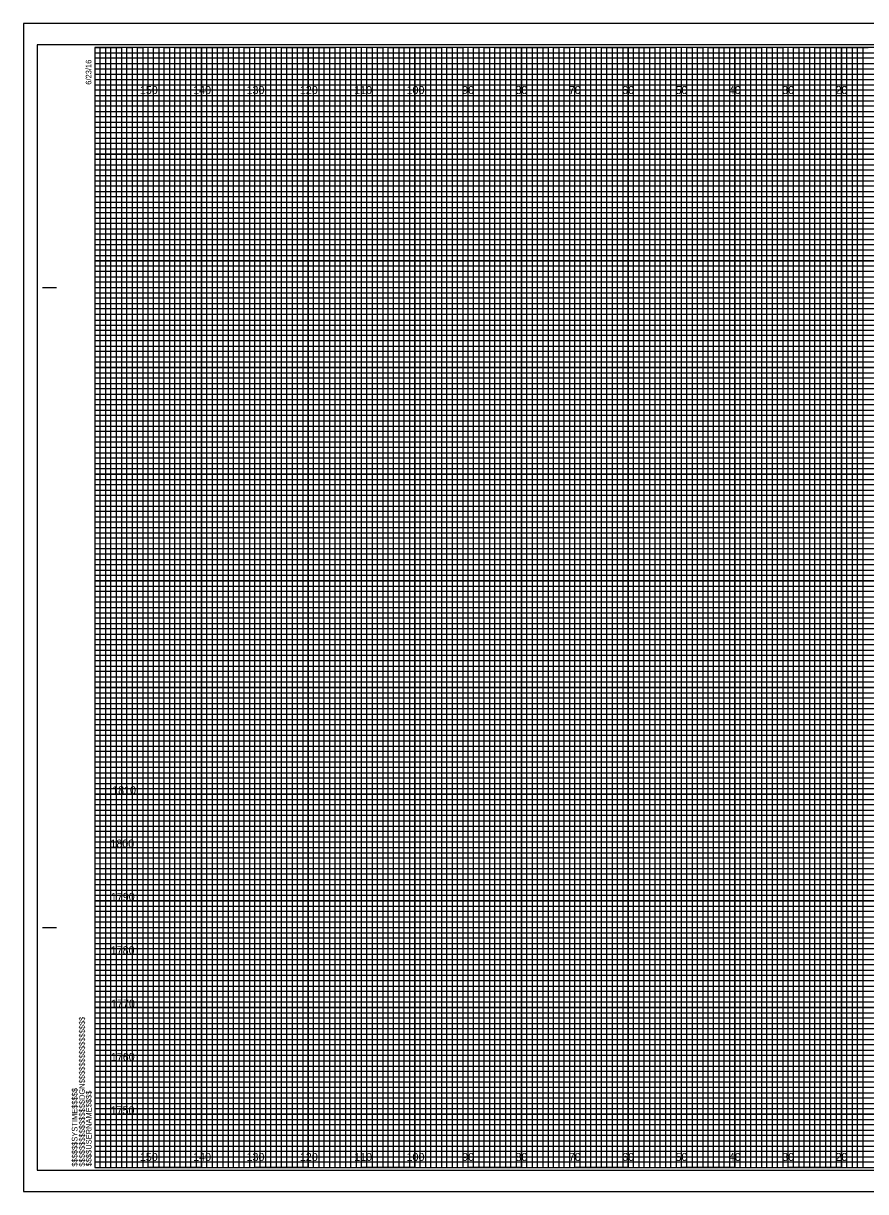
# Model space of a CAD drawing. Extents: x -13 to 323, y -5 to 874.
# Drawn here: x -13.4 to 144.5, y 655.5 to 874.5 of the extents above; entities that cross this region are included whole.
import ezdxf

# ---------------------------------------------------------------- set-up
doc = ezdxf.new("R2010")
doc.units = 0
for name, color, linetype in [('Prop XS Earthwork Shape', 7, 'Continuous'), ('Raster_Level_0', 7, 'Continuous'), ('Scratch_Level_1', 7, 'Continuous'), ('Scratch_Level_3', 7, 'Continuous'), ('Sheet Cross Section CELL', 7, 'Continuous'), ('Sheet Cross Section Grid Minor 1 CELL', 7, 'Continuous'), ('Sheet Cross Section Grid Minor 2 CELL', 7, 'Continuous'), ('Sheet Cutting Line CELL', 7, 'Continuous'), ('Sheet DOT Grid CELL', 7, 'Continuous'), ('Sheet Plot Border Inside CELL', 7, 'Continuous'), ('Sheet Plot Border Outside CELL', 7, 'Continuous')]:
    doc.layers.add(name, color=color, linetype=linetype)

msp = doc.modelspace()

# ---------------------------------------------------------------- linework, layer by layer
at = {"layer": 'Prop XS Earthwork Shape'}
for points in [[(0, 870), (5, 870), (5, 660), (15, 660), (15, 870), (25, 870), (25, 660), (35, 660), (35, 870), (45, 870), (45, 660), (55, 660), (55, 870), (65, 870), (65, 660), (75, 660), (75, 870), (85, 870), (85, 660), (95, 660), (95, 870), (105, 870), (105, 660), (115, 660), (115, 870), (125, 870), (125, 660), (135, 660), (135, 870), (145, 870)], [(0, 865), (275, 865)], [(0, 845), (320, 845), (320, 855), (0, 855)], [(0, 825), (320, 825), (320, 835), (0, 835)], [(0, 805), (320, 805), (320, 815), (0, 815)], [(0, 785), (320, 785), (320, 795), (0, 795)], [(0, 765), (320, 765), (320, 775), (0, 775)], [(0, 745), (320, 745), (320, 755), (0, 755)], [(0, 725), (320, 725), (320, 735), (0, 735)], [(0, 705), (320, 705), (320, 715), (0, 715)], [(0, 685), (320, 685), (320, 695), (0, 695)], [(0, 665), (320, 665), (320, 675), (0, 675)]]:
    msp.add_lwpolyline(points, dxfattribs=at)
at = {"layer": 'Scratch_Level_1'}
for p, q in [((10, 870), (0, 870)), ((10, 660), (10, 870)), ((30, 870), (20, 870)), ((20, 870), (20, 660)), ((30, 660), (30, 870)), ((50, 870), (40, 870)), ((40, 870), (40, 660)), ((50, 660), (50, 870)), ((70, 870), (60, 870)), ((60, 870), (60, 660)), ((70, 660), (70, 870)), ((90, 870), (80, 870)), ((80, 870), (80, 660)), ((90, 660), (90, 870)), ((110, 870), (100, 870)), ((100, 870), (100, 660)), ((110, 660), (110, 870)), ((130, 870), (120, 870)), ((120, 870), (120, 660)), ((130, 660), (130, 870)), ((150, 870), (140, 870)), ((140, 870), (140, 660)), ((20, 660), (10, 660)), ((40, 660), (30, 660)), ((60, 660), (50, 660)), ((80, 660), (70, 660)), ((100, 660), (90, 660)), ((120, 660), (110, 660)), ((140, 660), (130, 660))]:
    msp.add_line(p, q, dxfattribs=at)
for points in [[(0, 860), (320, 860), (320, 850), (0, 850)], [(0, 840), (320, 840), (320, 830), (0, 830)], [(0, 820), (320, 820), (320, 810), (0, 810)], [(0, 800), (320, 800), (320, 790), (0, 790)], [(0, 780), (320, 780), (320, 770), (0, 770)], [(0, 760), (320, 760), (320, 750), (0, 750)], [(0, 740), (320, 740), (320, 730), (0, 730)], [(0, 720), (320, 720), (320, 710), (0, 710)], [(0, 700), (320, 700), (320, 690), (0, 690)], [(0, 680), (320, 680), (320, 670), (0, 670)]]:
    msp.add_lwpolyline(points, dxfattribs=at)
at = {"layer": 'Sheet Cross Section CELL'}
for p, q in [((-9.8, 825), (-7.3, 825)), ((-9.7, 825), (-7.2, 825)), ((-9.8, 705), (-7.3, 705)), ((-9.7, 705), (-7.2, 705)), ((0, 660), (0, 660)), ((0, 660), (0, 660)), ((0, 660), (0, 660)), ((0, 660), (0, 660)), ((0, 660), (0, 660)), ((0, 660), (0, 660)), ((0, 660), (0, 660))]:
    msp.add_line(p, q, dxfattribs=at)
msp.add_lwpolyline([(320, 870), (0, 870), (0, 660), (320, 660)], close=True, dxfattribs=at)
at = {"layer": 'Sheet Cross Section Grid Minor 1 CELL'}
for p, q in [((0, 869), (260, 869)), ((260, 867.98), (0, 867.98)), ((0, 867.98), (0, 867)), ((0, 867), (260, 867)), ((260, 865.89), (0, 865.89)), ((0, 865.89), (0, 864)), ((0, 864), (320, 864))]:
    msp.add_line(p, q, dxfattribs=at)
for points in [[(0, 863), (270, 863), (320, 863), (320, 862), (0, 862)], [(0, 861), (320, 861), (320, 859), (0, 859)], [(0, 858), (320, 858), (320, 857), (0, 856.98)], [(0, 856), (320, 856), (320, 854), (0, 854)], [(0, 853), (320, 853), (320, 852), (0, 852)], [(0, 851), (320, 851), (320, 849), (0, 849)], [(0, 848), (320, 848), (320, 847), (0, 847)], [(0, 846), (320, 846), (320, 844), (0, 844)], [(0, 843), (320, 843), (320, 842), (0, 842)], [(0, 841), (320, 841), (320, 839), (0, 839)], [(0, 838), (320, 838), (320, 837), (0, 837)], [(0, 836), (320, 836), (320, 833.95), (320, 833), (320, 832), (0, 832)], [(0, 834), (320, 834), (320, 833), (0, 833)], [(0, 831), (320, 831), (320, 829), (0, 829.03)], [(0, 829.03), (320, 829), (320, 828), (0, 828)], [(0, 827), (320, 827), (320, 826), (0, 826)], [(0, 824), (320, 824), (320, 823), (0, 823)], [(0, 822), (320, 822), (320, 821), (0, 821)], [(-0.07, 818.89), (320, 818.89), (320, 817.88), (-0.07, 817.88)], [(0, 817), (320, 817), (320, 816), (0, 816)], [(0, 814), (320, 814), (320, 813), (0, 813)], [(0, 812), (320, 812), (320, 811), (0, 811)], [(0, 809), (320, 809), (320, 808), (0, 808)], [(0, 807), (320, 807), (320, 806), (0, 806)], [(0, 804), (320, 804), (320, 803), (0, 803)], [(0, 802), (320, 802), (320, 801), (0, 801)], [(0, 799), (320, 799), (319.99, 797.98), (0, 798)], [(0, 797), (320, 797), (320, 796), (0, 796)], [(0, 794), (320, 794), (320, 793), (0, 793)], [(0, 792), (320, 792), (320, 791), (0, 791)], [(0, 789), (320, 789), (320, 788), (0, 788)], [(0, 787), (320, 787), (320, 786), (0, 786)], [(0, 784), (320, 784), (320, 783), (0, 783)], [(0, 782), (320, 782), (320, 781), (0, 781)], [(0, 779), (320, 779), (320, 778), (0, 778)], [(0, 776.99), (320.07, 776.91), (320, 776), (0, 776)], [(0, 774), (320, 774), (320, 773), (0, 773)], [(0, 772), (320, 772), (320, 771), (0, 771)], [(0, 769), (320, 769), (320, 768), (0, 768)], [(0, 767), (320, 767), (320, 766), (0, 766)], [(0, 764), (320, 764), (320, 763), (0, 763)], [(0, 762), (320, 762), (320, 761), (0, 761)], [(0, 759), (320, 759), (320, 758), (0, 758)], [(0, 757), (320, 757), (320, 756), (0, 756)], [(0, 754), (320, 754), (320, 753), (0, 753)], [(0, 752), (320, 752), (320, 751), (0, 751)], [(0, 749), (320, 749), (320, 748), (0, 748)], [(0, 747), (320, 747), (320, 746), (0, 746)], [(0, 744), (320, 744), (320, 743), (0, 743)], [(0, 742), (320, 742), (320, 741), (0, 741)], [(0, 739), (320, 739), (319.99, 737.98), (0, 738)], [(0, 737), (320, 737), (320, 736), (0, 736)], [(0, 734), (320, 734), (320, 733), (0, 733)], [(0, 732), (320, 732), (320, 731), (0, 731)], [(0, 729), (320, 729), (320, 728), (0, 728)], [(0, 727), (320, 727), (320, 726), (0, 726)], [(0, 724), (320, 724), (320, 723), (0, 723)], [(0, 722), (320, 722), (320, 721), (0, 721)], [(0, 719), (320, 719), (320, 718), (0, 718)], [(0, 716.99), (320.07, 716.91), (320, 716), (0, 716)], [(0, 714), (320, 714), (320, 713), (0, 713)], [(0, 712), (320, 712), (320, 711), (0, 711)], [(0, 709), (320, 709), (320, 708), (0, 708)], [(0, 707), (320, 707), (320, 706), (0, 706)], [(0, 704), (320, 704), (320, 703), (0, 703)], [(0, 702), (320, 702), (320, 701), (0, 701)], [(0, 699), (320, 699), (320, 698), (0, 698)], [(0, 697), (320, 697), (320, 696), (0, 696)], [(0, 694), (320, 694), (320, 693), (0, 693)], [(0, 692), (320, 692), (320, 691), (0, 691)], [(0, 689), (320, 689), (320, 688), (0, 688)], [(0, 687), (320, 687), (320, 686), (0, 686)], [(0, 684), (320, 684), (320, 683), (0, 683)], [(0, 682), (320, 682), (320, 681), (0, 681)], [(0, 679), (320, 679), (320, 678), (0, 678)], [(0, 677), (320, 677), (320, 676), (0, 676)], [(0, 674), (320, 674), (320, 673), (0, 673)], [(0, 672), (320, 672), (320, 671), (0, 671)], [(0, 669), (320, 669), (320, 668), (0, 668)], [(0, 667), (320, 667), (320, 666), (0, 666)], [(0, 664), (320, 664), (320, 663), (0, 663)], [(0, 662), (320, 662), (320, 661), (0, 661)]]:
    msp.add_lwpolyline(points, dxfattribs=at)
at = {"layer": 'Sheet Cross Section Grid Minor 2 CELL'}
for points in [[(0, 660), (1, 660), (1, 870), (2, 870), (2, 660)], [(2, 660), (3, 660), (3, 870), (4, 870), (4, 660)], [(5, 660), (6, 660), (6, 870), (7, 870), (7, 660)], [(7, 660), (8, 660), (8, 870), (9, 870), (9, 660)], [(10, 660), (11, 660), (11, 870), (12, 870), (12, 660)], [(12, 660), (13, 660), (13, 870), (14, 870), (14, 660)], [(15, 660), (16, 660), (16, 870), (17, 870), (17, 660)], [(17, 660), (18, 660), (18, 870), (19, 870), (19, 660)], [(20, 660), (21, 660), (21, 870), (22, 870), (22, 660)], [(22, 660), (23, 660), (23, 870), (24, 870), (24, 660)], [(25, 660), (26, 660), (26, 870), (27, 870), (27, 660)], [(27, 660), (28, 660), (28, 870), (29, 870), (29, 660)], [(30, 660), (31, 660), (31, 870), (32, 870), (32, 660)], [(32, 660), (33, 660), (33, 870), (34, 870), (34, 660)], [(35, 660), (36, 660), (36, 870), (37, 870), (37, 660)], [(37, 660), (38, 660), (38, 870), (39, 870), (39, 660)], [(40, 660), (41, 660), (41, 870), (42, 870), (42, 660)], [(42, 660), (43, 660), (43, 870), (44, 870), (44, 660)], [(45, 660), (46, 660), (46, 870), (47, 870), (47, 660)], [(47, 660), (48, 660), (48, 870), (49, 870), (49, 660)], [(50, 660), (51, 660), (51, 870), (52, 870), (52, 660)], [(52, 660), (53, 660), (53, 870), (54, 870), (54, 660)], [(55, 660), (56, 660), (56, 870), (57, 870), (57, 660)], [(57, 660), (58, 660), (58, 870), (59, 870), (59, 660)], [(60, 660), (61, 660), (61, 870), (62, 870), (62, 660)], [(62, 660), (63, 660), (63, 870), (64, 870), (64, 660)], [(65, 660), (66, 660), (66, 870), (67, 870), (67, 660)], [(67, 660), (68, 660), (68, 870), (69, 870), (69, 660)], [(70, 660), (71, 660), (71, 870), (72, 870), (72, 660)], [(72, 660), (73, 660), (73, 870), (74, 870), (74, 660)], [(75, 660), (76, 660), (76, 870), (77, 870), (77, 660)], [(77, 660), (78, 660), (78, 870), (79, 870), (79, 660)], [(80, 660), (81, 660), (81, 870), (82, 870), (82, 660)], [(82, 660), (83, 660), (83, 870), (84, 870), (84, 660)], [(85, 660), (86, 660), (86, 870), (87, 870), (87, 660)], [(87, 660), (88, 660), (88, 870), (89, 870), (89, 660)], [(90, 660), (91, 660), (91, 870), (92, 870), (92, 660)], [(92, 660), (93, 660), (93, 870), (94, 870), (94, 660)], [(95, 660), (96, 660), (96, 870), (97, 870), (97, 660)], [(97, 660), (98, 660), (98, 870), (99, 870), (99, 660)], [(100, 660), (101, 660), (101, 870), (102, 870), (102, 660)], [(102, 660), (103, 660), (103, 870), (104, 870), (104, 660)], [(105, 660), (106, 660), (106, 870), (107, 870), (107, 660)], [(107, 660), (108, 660), (108, 870), (109, 870), (109, 660)], [(110, 660), (111, 660), (111, 870), (112, 870), (112, 660)], [(112, 660), (113, 660), (113, 870), (114, 870), (114, 660)], [(115, 660), (116, 660), (116, 870), (117, 870), (117, 660)], [(117, 660), (118, 660), (118, 870), (119, 870), (119, 660)], [(120, 660), (121, 660), (121, 870), (122, 870), (122, 660)], [(122, 660), (123, 660), (123, 870), (124, 870), (124, 660)], [(125, 660), (126, 660), (126, 870), (127, 870), (127, 660)], [(127, 660), (128, 660), (128, 870), (129, 870), (129, 660)], [(130, 660), (131, 660), (131, 870), (132, 870), (132, 660)], [(132, 660), (133, 660), (133, 870), (134, 870), (134, 660)], [(135, 660), (136, 660), (136, 870), (137, 870), (137, 660)], [(137, 660), (138, 660), (138, 870), (139, 870), (139, 660)], [(140, 660), (141, 660), (141, 870), (142, 870), (142, 660)], [(142, 660), (143, 660), (143, 870), (144, 870), (144, 660)]]:
    msp.add_lwpolyline(points, dxfattribs=at)
at = {"layer": 'Sheet Cutting Line CELL'}
for p, q in [((323.3, 874.5), (-13.4, 874.5)), ((-13.4, 874.5), (-13.4, 655.5)), ((-13.4, 655.5), (323.3, 655.5))]:
    msp.add_line(p, q, dxfattribs=at)
at = {"layer": 'Sheet DOT Grid CELL'}
for p, q in [((10, 660), (10, 870)), ((20, 660), (20, 870)), ((30, 660), (30, 870)), ((40, 660), (40, 870)), ((50, 660), (50, 870)), ((60, 660), (60, 870)), ((70, 660), (70, 870)), ((80, 660), (80, 870)), ((90, 660), (90, 870)), ((100, 660), (100, 870)), ((110, 660), (110, 870)), ((120, 660), (120, 870)), ((130, 660), (130, 870)), ((140, 660), (140, 870)), ((0, 860), (320, 860)), ((0, 850), (320, 850)), ((0, 840), (320, 840)), ((0, 830), (320, 830)), ((0, 820), (320, 820)), ((0, 810), (320, 810)), ((0, 800), (320, 800)), ((0, 790), (320, 790)), ((0, 780), (320, 780)), ((0, 770), (320, 770)), ((0, 760), (320, 760)), ((0, 750), (320, 750)), ((0, 740), (320, 740)), ((0, 730), (320, 730)), ((0, 720), (320, 720)), ((0, 710), (320, 710)), ((0, 700), (320, 700)), ((0, 690), (320, 690)), ((0, 680), (320, 680)), ((0, 670), (320, 670))]:
    msp.add_line(p, q, dxfattribs=at)
at = {"layer": 'Sheet Plot Border Inside CELL'}
msp.add_lwpolyline([(-10.8, 659.5), (322.4, 659.5), (322.4, 870.5), (-10.8, 870.5)], close=True, dxfattribs=at)
at = {"layer": 'Sheet Plot Border Outside CELL'}
msp.add_lwpolyline([(-13.4, 655.5), (323.3, 655.5), (323.3, 874.5), (-13.4, 874.5)], close=True, dxfattribs=at)

# ---------------------------------------------------------------- texts
at = {"layer": 'Raster_Level_0'}
for s, p in [('150', (8.44, 861.25)), ('140', (18.44, 861.25)), ('130', (28.44, 861.25)), ('120', (38.44, 861.25)), ('110', (48.62, 861.25)), ('100', (58.44, 861.25)), ('90', (68.86, 861.25)), ('80', (78.86, 861.25)), ('70', (88.86, 861.25)), ('60', (98.86, 861.25)), ('50', (108.86, 861.25)), ('40', (118.86, 861.25)), ('30', (128.86, 861.25)), ('20', (138.86, 861.25)), ('150', (8.44, 661.25)), ('140', (18.44, 661.25)), ('130', (28.44, 661.25)), ('120', (38.44, 661.25)), ('110', (48.62, 661.25)), ('100', (58.44, 661.25)), ('90', (68.86, 661.25)), ('80', (78.86, 661.25)), ('70', (88.86, 661.25)), ('60', (98.86, 661.25)), ('50', (108.86, 661.25)), ('40', (118.86, 661.25)), ('30', (128.86, 661.25)), ('20', (138.86, 661.25))]:
    msp.add_text(s, height=1.5, dxfattribs=at).set_placement(p)
at = {"layer": 'Scratch_Level_3'}
for s, p in [('1810', (3.25, 730)), ('1800', (2.92, 720)), ('1790', (3, 710)), ('1780', (2.98, 700)), ('1770', (3.04, 690)), ('1760', (3, 680)), ('1750', (2.96, 670))]:
    msp.add_text(s, height=1.5, dxfattribs=at).set_placement(p)
at = {"layer": 'Sheet Cross Section CELL'}
for s, p in [('6/23/16', (-0.65, 863)), ('$$$$$$$$$$$$$$$$DGN$$$$$$$$$$$$$$$$', (-1.88, 660.18)), ('$$$$$$SYSTIME$$$$$', (-3.26, 660.18)), ('$$$$USERNAME$$$$', (-0.62, 660.23))]:
    msp.add_text(s, height=1.05, rotation=90, dxfattribs=at).set_placement(p)

doc.saveas('drawing.dxf')
